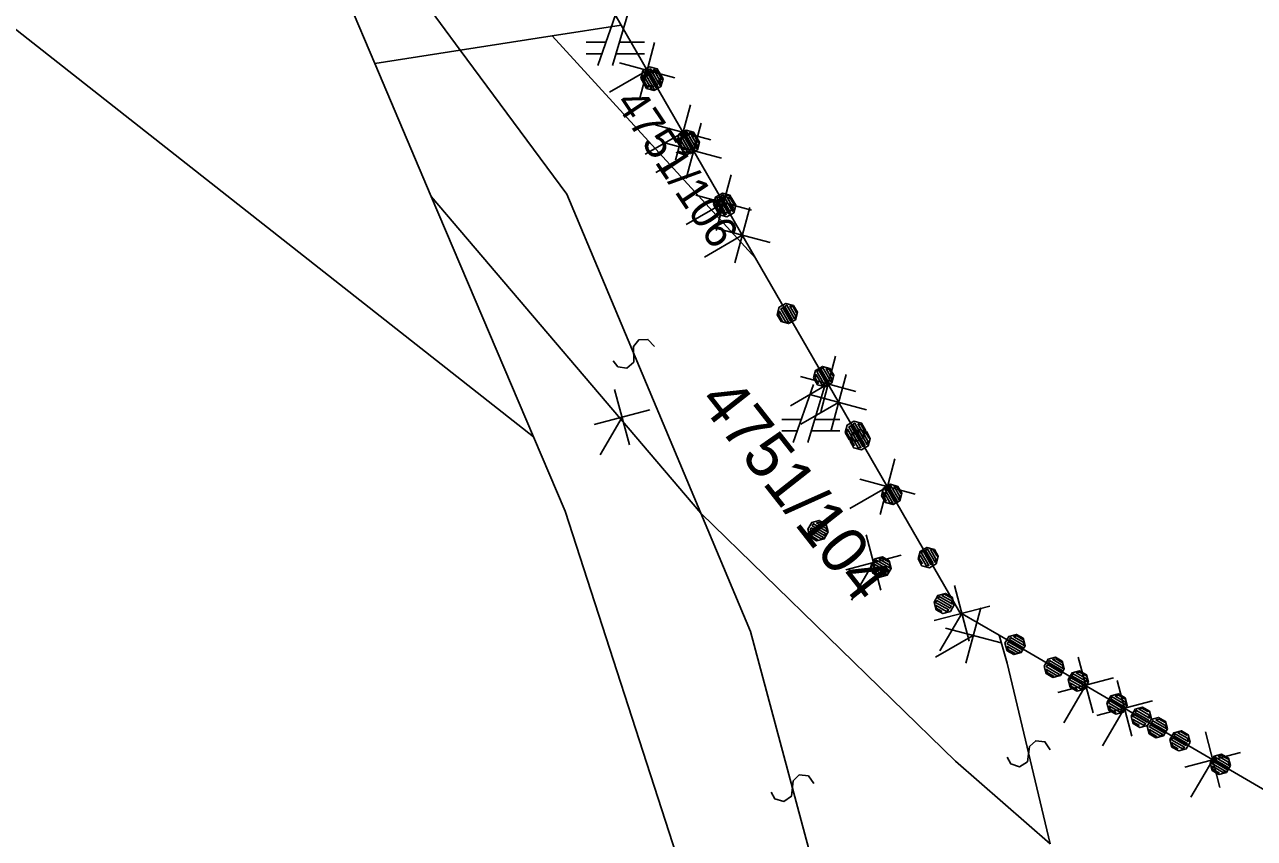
# Model space of a CAD drawing. Extents: x -266179 to -264727, y -1243225 to -1241702.
# Drawn here: x -264955.06 to -264912.71, y -1242293.44 to -1242265.42 of the extents above; entities that cross this region are included whole.
import ezdxf

# ---------------------------------------------------------------- set-up
doc = ezdxf.new("R2010")
doc.units = 0
for name, color, linetype in [('Vrstva 1', 7, 'Continuous'), ('Vrstva 19', 7, 'Continuous'), ('Vrstva 2', 7, 'Continuous'), ('Vrstva 21', 7, 'Continuous')]:
    doc.layers.add(name, color=color, linetype=linetype)

msp = doc.modelspace()

# ---------------------------------------------------------------- linework, layer by layer
at = {"layer": 'Vrstva 1'}
for p, q in [((-264937.54, -1242279.61), (-265000.5, -1242230.1)), ((-264938.49, -1242258.56), (-264934.52, -1242265.43)), ((-264943, -1242266.76), (-264943.91, -1242264.62)), ((-264934.62, -1242264.82), (-264935.32, -1242266.82)), ((-264934.82, -1242266.82), (-264934.22, -1242264.82)), ((-264936.9, -1242265.8), (-264934.52, -1242265.43)), ((-264934.52, -1242265.43), (-264929.89, -1242273.46)), ((-264940.06, -1242266.3), (-264936.9, -1242265.8)), ((-264936.9, -1242265.8), (-264940.06, -1242266.3)), ((-264929.89, -1242273.46), (-264936.9, -1242265.8)), ((-264936.9, -1242265.8), (-264929.89, -1242273.46)), ((-264935.04, -1242266.02), (-264935.72, -1242266.02)), ((-264933.72, -1242266.02), (-264934.58, -1242266.02)), ((-264943, -1242266.76), (-264940.06, -1242266.3)), ((-264940.06, -1242266.3), (-264943, -1242266.76)), ((-264935.72, -1242266.42), (-264935.18, -1242266.42)), ((-264934.7, -1242266.42), (-264933.72, -1242266.42)), ((-264941.06, -1242271.34), (-264943, -1242266.76)), ((-264931.78, -1242282.24), (-264941.06, -1242271.34)), ((-264937.54, -1242279.61), (-264941.06, -1242271.34)), ((-264941.06, -1242271.34), (-264931.78, -1242282.24)), ((-264929.89, -1242273.46), (-264922.85, -1242285.66)), ((-264927.89, -1242277.81), (-264928.59, -1242279.81)), ((-264928.09, -1242279.81), (-264927.49, -1242277.81)), ((-264928.31, -1242279.01), (-264928.99, -1242279.01)), ((-264926.99, -1242279.01), (-264927.85, -1242279.01)), ((-264936.45, -1242282.17), (-264937.54, -1242279.61)), ((-264928.99, -1242279.41), (-264928.45, -1242279.41)), ((-264927.97, -1242279.41), (-264926.99, -1242279.41)), ((-264931.05, -1242298.84), (-264936.45, -1242282.17)), ((-264923, -1242290.78), (-264931.78, -1242282.24)), ((-264931.78, -1242282.24), (-264923, -1242290.78)), ((-264922.85, -1242285.66), (-264921.5, -1242286.44)), ((-264921.5, -1242286.44), (-264909.83, -1242293.25)), ((-264919.74, -1242293.63), (-264923, -1242290.78)), ((-264923, -1242290.78), (-264919.74, -1242293.63))]:
    msp.add_line(p, q, dxfattribs=at)
at = {"layer": 'Vrstva 19'}
for p, q in [((-264938.49, -1242258.56), (-264934.52, -1242265.43)), ((-264934.52, -1242265.43), (-264929.89, -1242273.46)), ((-264929.89, -1242273.46), (-264922.85, -1242285.66)), ((-264922.85, -1242285.66), (-264921.5, -1242286.44)), ((-264921.5, -1242286.44), (-264909.83, -1242293.25))]:
    msp.add_line(p, q, dxfattribs=at)
for points in [[(-264933.143, -1242267.175), (-264933.213, -1242267.434), (-264933.447, -1242267.569), (-264933.707, -1242267.499), (-264933.841, -1242267.265), (-264933.772, -1242267.006), (-264933.538, -1242266.871), (-264933.278, -1242266.941), (-264933.143, -1242267.175), (-264933.173, -1242267.204), (-264933.293, -1242266.996), (-264933.402, -1242266.966), (-264933.202, -1242267.313), (-264933.242, -1242267.405), (-264933.511, -1242266.937), (-264933.581, -1242266.977), (-264933.316, -1242267.436), (-264933.38, -1242267.485), (-264933.645, -1242267.025), (-264933.714, -1242267.065), (-264933.45, -1242267.525), (-264933.544, -1242267.521), (-264933.759, -1242267.149), (-264933.793, -1242267.249), (-264933.653, -1242267.492)], [(-264933.078, -1242267.288), (-264933.148, -1242267.548), (-264933.382, -1242267.683), (-264933.641, -1242267.613), (-264933.776, -1242267.379), (-264933.706, -1242267.119), (-264933.472, -1242266.985), (-264933.213, -1242267.054), (-264933.078, -1242267.288), (-264933.108, -1242267.317), (-264933.227, -1242267.109), (-264933.337, -1242267.08), (-264933.137, -1242267.426), (-264933.176, -1242267.518), (-264933.446, -1242267.05), (-264933.515, -1242267.09), (-264933.251, -1242267.549), (-264933.315, -1242267.598), (-264933.58, -1242267.139), (-264933.649, -1242267.179), (-264933.384, -1242267.638), (-264933.479, -1242267.634), (-264933.693, -1242267.262), (-264933.728, -1242267.362), (-264933.588, -1242267.605)], [(-264931.891, -1242269.35), (-264931.96, -1242269.609), (-264932.194, -1242269.744), (-264932.454, -1242269.674), (-264932.589, -1242269.44), (-264932.519, -1242269.181), (-264932.285, -1242269.046), (-264932.025, -1242269.116), (-264931.891, -1242269.35), (-264931.93, -1242269.361), (-264932.05, -1242269.153), (-264932.159, -1242269.124), (-264931.96, -1242269.47), (-264931.989, -1242269.58), (-264932.268, -1242269.094), (-264932.338, -1242269.134), (-264932.058, -1242269.62), (-264932.128, -1242269.66), (-264932.407, -1242269.174), (-264932.476, -1242269.214), (-264932.197, -1242269.7), (-264932.306, -1242269.67), (-264932.506, -1242269.324), (-264932.535, -1242269.433), (-264932.415, -1242269.641)], [(-264931.825, -1242269.463), (-264931.895, -1242269.723), (-264932.129, -1242269.857), (-264932.388, -1242269.788), (-264932.523, -1242269.554), (-264932.453, -1242269.294), (-264932.219, -1242269.159), (-264931.96, -1242269.229), (-264931.825, -1242269.463), (-264931.865, -1242269.475), (-264931.985, -1242269.267), (-264932.094, -1242269.237), (-264931.894, -1242269.584), (-264931.924, -1242269.693), (-264932.203, -1242269.208), (-264932.272, -1242269.248), (-264931.993, -1242269.733), (-264932.062, -1242269.773), (-264932.342, -1242269.288), (-264932.411, -1242269.328), (-264932.132, -1242269.813), (-264932.241, -1242269.783), (-264932.44, -1242269.437), (-264932.47, -1242269.546), (-264932.35, -1242269.754)], [(-264930.638, -1242271.525), (-264930.707, -1242271.784), (-264930.941, -1242271.919), (-264931.201, -1242271.849), (-264931.336, -1242271.615), (-264931.266, -1242271.356), (-264931.032, -1242271.221), (-264930.772, -1242271.291), (-264930.638, -1242271.525), (-264930.692, -1242271.51), (-264930.812, -1242271.302), (-264930.911, -1242271.29), (-264930.722, -1242271.619), (-264930.751, -1242271.729), (-264931.011, -1242271.278), (-264931.08, -1242271.318), (-264930.82, -1242271.769), (-264930.89, -1242271.809), (-264931.149, -1242271.358), (-264931.224, -1242271.389), (-264930.964, -1242271.84), (-264931.053, -1242271.845), (-264931.258, -1242271.49), (-264931.302, -1242271.573), (-264931.183, -1242271.781)], [(-264930.572, -1242271.638), (-264930.642, -1242271.898), (-264930.876, -1242272.032), (-264931.136, -1242271.963), (-264931.27, -1242271.729), (-264931.201, -1242271.469), (-264930.967, -1242271.334), (-264930.707, -1242271.404), (-264930.572, -1242271.638), (-264930.627, -1242271.624), (-264930.747, -1242271.416), (-264930.846, -1242271.403), (-264930.656, -1242271.733), (-264930.686, -1242271.842), (-264930.945, -1242271.391), (-264931.015, -1242271.431), (-264930.755, -1242271.882), (-264930.824, -1242271.922), (-264931.084, -1242271.471), (-264931.158, -1242271.503), (-264930.899, -1242271.953), (-264930.988, -1242271.958), (-264931.193, -1242271.603), (-264931.237, -1242271.686), (-264931.117, -1242271.894)], [(-264928.449, -1242275.318), (-264928.518, -1242275.578), (-264928.752, -1242275.713), (-264929.012, -1242275.643), (-264929.147, -1242275.41), (-264929.077, -1242275.15), (-264928.843, -1242275.015), (-264928.584, -1242275.085), (-264928.449, -1242275.318), (-264928.478, -1242275.347), (-264928.598, -1242275.139), (-264928.708, -1242275.11), (-264928.508, -1242275.456), (-264928.547, -1242275.548), (-264928.817, -1242275.081), (-264928.886, -1242275.121), (-264928.621, -1242275.58), (-264928.686, -1242275.628), (-264928.951, -1242275.169), (-264929.02, -1242275.209), (-264928.755, -1242275.668), (-264928.849, -1242275.665), (-264929.064, -1242275.293), (-264929.098, -1242275.393), (-264928.958, -1242275.636)], [(-264927.194, -1242277.492), (-264927.263, -1242277.752), (-264927.497, -1242277.887), (-264927.757, -1242277.817), (-264927.892, -1242277.583), (-264927.822, -1242277.324), (-264927.588, -1242277.189), (-264927.329, -1242277.258), (-264927.194, -1242277.492), (-264927.233, -1242277.503), (-264927.353, -1242277.296), (-264927.463, -1242277.266), (-264927.263, -1242277.613), (-264927.292, -1242277.722), (-264927.572, -1242277.237), (-264927.641, -1242277.277), (-264927.361, -1242277.762), (-264927.431, -1242277.802), (-264927.711, -1242277.317), (-264927.78, -1242277.357), (-264927.5, -1242277.842), (-264927.609, -1242277.813), (-264927.809, -1242277.466), (-264927.838, -1242277.576), (-264927.718, -1242277.783)], [(-264926.107, -1242279.377), (-264926.177, -1242279.636), (-264926.41, -1242279.771), (-264926.67, -1242279.702), (-264926.805, -1242279.468), (-264926.735, -1242279.208), (-264926.502, -1242279.073), (-264926.242, -1242279.143), (-264926.107, -1242279.377), (-264926.137, -1242279.405), (-264926.257, -1242279.197), (-264926.366, -1242279.168), (-264926.166, -1242279.515), (-264926.205, -1242279.607), (-264926.475, -1242279.139), (-264926.544, -1242279.179), (-264926.279, -1242279.638), (-264926.344, -1242279.687), (-264926.609, -1242279.228), (-264926.678, -1242279.268), (-264926.413, -1242279.727), (-264926.507, -1242279.723), (-264926.722, -1242279.351), (-264926.757, -1242279.452), (-264926.617, -1242279.694)], [(-264925.939, -1242279.666), (-264926.008, -1242279.925), (-264926.242, -1242280.06), (-264926.502, -1242279.991), (-264926.637, -1242279.757), (-264926.567, -1242279.497), (-264926.333, -1242279.362), (-264926.074, -1242279.432), (-264925.939, -1242279.666), (-264925.993, -1242279.651), (-264926.113, -1242279.443), (-264926.213, -1242279.431), (-264926.023, -1242279.76), (-264926.052, -1242279.87), (-264926.312, -1242279.419), (-264926.381, -1242279.459), (-264926.121, -1242279.91), (-264926.191, -1242279.95), (-264926.451, -1242279.499), (-264926.525, -1242279.531), (-264926.265, -1242279.981), (-264926.354, -1242279.986), (-264926.559, -1242279.631), (-264926.603, -1242279.715), (-264926.483, -1242279.923)], [(-264924.852, -1242281.55), (-264924.921, -1242281.81), (-264925.155, -1242281.945), (-264925.415, -1242281.875), (-264925.55, -1242281.642), (-264925.48, -1242281.382), (-264925.247, -1242281.247), (-264924.987, -1242281.317), (-264924.852, -1242281.55), (-264924.892, -1242281.562), (-264925.012, -1242281.354), (-264925.121, -1242281.325), (-264924.921, -1242281.671), (-264924.95, -1242281.78), (-264925.23, -1242281.295), (-264925.299, -1242281.335), (-264925.019, -1242281.82), (-264925.089, -1242281.86), (-264925.369, -1242281.375), (-264925.438, -1242281.415), (-264925.158, -1242281.9), (-264925.267, -1242281.871), (-264925.467, -1242281.525), (-264925.497, -1242281.634), (-264925.377, -1242281.842)], [(-264927.461, -1242282.625), (-264927.392, -1242282.885), (-264927.527, -1242283.119), (-264927.787, -1242283.188), (-264928.02, -1242283.053), (-264928.09, -1242282.793), (-264927.955, -1242282.56), (-264927.695, -1242282.49), (-264927.461, -1242282.625), (-264927.473, -1242282.665), (-264927.68, -1242282.545), (-264927.79, -1242282.574), (-264927.443, -1242282.774), (-264927.431, -1242282.874), (-264927.899, -1242282.603), (-264927.939, -1242282.673), (-264927.48, -1242282.938), (-264927.512, -1242283.012), (-264927.97, -1242282.747), (-264928.01, -1242282.816), (-264927.552, -1242283.081), (-264927.635, -1242283.126), (-264928.007, -1242282.91), (-264927.987, -1242283.015), (-264927.744, -1242283.155)], [(-264923.597, -1242283.724), (-264923.666, -1242283.984), (-264923.9, -1242284.119), (-264924.16, -1242284.049), (-264924.295, -1242283.815), (-264924.225, -1242283.556), (-264923.991, -1242283.421), (-264923.732, -1242283.49), (-264923.597, -1242283.724), (-264923.652, -1242283.709), (-264923.772, -1242283.502), (-264923.871, -1242283.49), (-264923.681, -1242283.819), (-264923.71, -1242283.928), (-264923.97, -1242283.478), (-264924.039, -1242283.518), (-264923.779, -1242283.968), (-264923.849, -1242284.008), (-264924.109, -1242283.558), (-264924.183, -1242283.589), (-264923.923, -1242284.039), (-264924.012, -1242284.045), (-264924.217, -1242283.69), (-264924.262, -1242283.773), (-264924.142, -1242283.981)], [(-264925.288, -1242283.882), (-264925.219, -1242284.141), (-264925.354, -1242284.375), (-264925.614, -1242284.444), (-264925.847, -1242284.309), (-264925.917, -1242284.05), (-264925.782, -1242283.816), (-264925.522, -1242283.747), (-264925.288, -1242283.882), (-264925.317, -1242283.911), (-264925.525, -1242283.791), (-264925.634, -1242283.82), (-264925.288, -1242284.021), (-264925.258, -1242284.13), (-264925.743, -1242283.85), (-264925.783, -1242283.919), (-264925.298, -1242284.199), (-264925.339, -1242284.268), (-264925.823, -1242283.988), (-264925.863, -1242284.057), (-264925.379, -1242284.338), (-264925.488, -1242284.367), (-264925.834, -1242284.167), (-264925.805, -1242284.276), (-264925.597, -1242284.396)], [(-264923.115, -1242285.138), (-264923.046, -1242285.398), (-264923.181, -1242285.631), (-264923.441, -1242285.701), (-264923.674, -1242285.566), (-264923.744, -1242285.306), (-264923.609, -1242285.072), (-264923.349, -1242285.003), (-264923.115, -1242285.138), (-264923.17, -1242285.153), (-264923.378, -1242285.032), (-264923.47, -1242285.072), (-264923.141, -1242285.262), (-264923.111, -1242285.371), (-264923.562, -1242285.111), (-264923.602, -1242285.18), (-264923.151, -1242285.44), (-264923.192, -1242285.51), (-264923.642, -1242285.249), (-264923.69, -1242285.314), (-264923.24, -1242285.574), (-264923.315, -1242285.623), (-264923.67, -1242285.418), (-264923.667, -1242285.512), (-264923.459, -1242285.632)], [(-264920.672, -1242286.548), (-264920.603, -1242286.808), (-264920.738, -1242287.041), (-264920.997, -1242287.111), (-264921.231, -1242286.976), (-264921.301, -1242286.716), (-264921.165, -1242286.482), (-264920.906, -1242286.413), (-264920.672, -1242286.548), (-264920.683, -1242286.588), (-264920.891, -1242286.468), (-264921, -1242286.497), (-264920.654, -1242286.697), (-264920.642, -1242286.796), (-264921.11, -1242286.526), (-264921.15, -1242286.595), (-264920.691, -1242286.861), (-264920.722, -1242286.935), (-264921.181, -1242286.67), (-264921.221, -1242286.739), (-264920.762, -1242287.004), (-264920.846, -1242287.048), (-264921.218, -1242286.833), (-264921.197, -1242286.937), (-264920.955, -1242287.078)], [(-264919.326, -1242287.338), (-264919.258, -1242287.598), (-264919.394, -1242287.831), (-264919.654, -1242287.899), (-264919.887, -1242287.763), (-264919.956, -1242287.504), (-264919.819, -1242287.27), (-264919.56, -1242287.202), (-264919.326, -1242287.338), (-264919.338, -1242287.378), (-264919.545, -1242287.257), (-264919.655, -1242287.285), (-264919.309, -1242287.487), (-264919.298, -1242287.586), (-264919.764, -1242287.314), (-264919.804, -1242287.383), (-264919.347, -1242287.65), (-264919.378, -1242287.725), (-264919.836, -1242287.457), (-264919.876, -1242287.527), (-264919.419, -1242287.794), (-264919.502, -1242287.838), (-264919.873, -1242287.621), (-264919.853, -1242287.725), (-264919.611, -1242287.866)], [(-264918.499, -1242287.804), (-264918.43, -1242288.064), (-264918.565, -1242288.298), (-264918.824, -1242288.367), (-264919.058, -1242288.232), (-264919.128, -1242287.972), (-264918.992, -1242287.739), (-264918.733, -1242287.669), (-264918.499, -1242287.804), (-264918.528, -1242287.834), (-264918.736, -1242287.714), (-264918.845, -1242287.743), (-264918.499, -1242287.943), (-264918.469, -1242288.053), (-264918.954, -1242287.772), (-264918.994, -1242287.842), (-264918.509, -1242288.122), (-264918.549, -1242288.191), (-264919.034, -1242287.911), (-264919.074, -1242287.98), (-264918.589, -1242288.26), (-264918.699, -1242288.29), (-264919.045, -1242288.089), (-264919.016, -1242288.199), (-264918.808, -1242288.319)], [(-264917.158, -1242288.603), (-264917.09, -1242288.863), (-264917.226, -1242289.096), (-264917.486, -1242289.164), (-264917.719, -1242289.028), (-264917.788, -1242288.768), (-264917.651, -1242288.535), (-264917.392, -1242288.467), (-264917.158, -1242288.603), (-264917.187, -1242288.633), (-264917.395, -1242288.512), (-264917.504, -1242288.54), (-264917.158, -1242288.742), (-264917.13, -1242288.851), (-264917.613, -1242288.569), (-264917.654, -1242288.638), (-264917.17, -1242288.92), (-264917.21, -1242288.99), (-264917.694, -1242288.707), (-264917.734, -1242288.776), (-264917.251, -1242289.059), (-264917.36, -1242289.087), (-264917.706, -1242288.886), (-264917.677, -1242288.995), (-264917.469, -1242289.116)], [(-264916.326, -1242289.061), (-264916.257, -1242289.32), (-264916.392, -1242289.554), (-264916.651, -1242289.623), (-264916.885, -1242289.488), (-264916.955, -1242289.229), (-264916.819, -1242288.995), (-264916.56, -1242288.925), (-264916.326, -1242289.061), (-264916.381, -1242289.075), (-264916.589, -1242288.955), (-264916.68, -1242288.994), (-264916.352, -1242289.185), (-264916.322, -1242289.294), (-264916.772, -1242289.034), (-264916.813, -1242289.103), (-264916.362, -1242289.363), (-264916.402, -1242289.432), (-264916.853, -1242289.172), (-264916.901, -1242289.236), (-264916.451, -1242289.497), (-264916.526, -1242289.546), (-264916.881, -1242289.341), (-264916.877, -1242289.435), (-264916.67, -1242289.555)], [(-264915.775, -1242289.41), (-264915.707, -1242289.67), (-264915.843, -1242289.903), (-264916.103, -1242289.972), (-264916.336, -1242289.836), (-264916.404, -1242289.576), (-264916.268, -1242289.343), (-264916.008, -1242289.274), (-264915.775, -1242289.41), (-264915.787, -1242289.45), (-264915.994, -1242289.329), (-264916.103, -1242289.358), (-264915.758, -1242289.559), (-264915.746, -1242289.659), (-264916.213, -1242289.387), (-264916.253, -1242289.456), (-264915.795, -1242289.723), (-264915.827, -1242289.797), (-264916.285, -1242289.53), (-264916.325, -1242289.599), (-264915.867, -1242289.866), (-264915.951, -1242289.91), (-264916.322, -1242289.693), (-264916.302, -1242289.798), (-264916.06, -1242289.939)], [(-264914.99, -1242289.868), (-264914.922, -1242290.128), (-264915.058, -1242290.361), (-264915.318, -1242290.429), (-264915.551, -1242290.293), (-264915.62, -1242290.033), (-264915.484, -1242289.8), (-264915.224, -1242289.732), (-264914.99, -1242289.868), (-264915.045, -1242289.882), (-264915.252, -1242289.761), (-264915.345, -1242289.8), (-264915.016, -1242289.992), (-264914.988, -1242290.101), (-264915.437, -1242289.839), (-264915.477, -1242289.908), (-264915.028, -1242290.17), (-264915.068, -1242290.239), (-264915.517, -1242289.977), (-264915.566, -1242290.041), (-264915.117, -1242290.303), (-264915.192, -1242290.352), (-264915.546, -1242290.146), (-264915.543, -1242290.24), (-264915.336, -1242290.361)], [(-264913.607, -1242290.675), (-264913.539, -1242290.935), (-264913.675, -1242291.168), (-264913.935, -1242291.237), (-264914.168, -1242291.101), (-264914.236, -1242290.841), (-264914.1, -1242290.608), (-264913.84, -1242290.539), (-264913.607, -1242290.675), (-264913.636, -1242290.705), (-264913.843, -1242290.584), (-264913.953, -1242290.613), (-264913.607, -1242290.814), (-264913.578, -1242290.924), (-264914.062, -1242290.641), (-264914.102, -1242290.711), (-264913.619, -1242290.993), (-264913.659, -1242291.062), (-264914.143, -1242290.78), (-264914.183, -1242290.849), (-264913.699, -1242291.131), (-264913.809, -1242291.16), (-264914.154, -1242290.958), (-264914.126, -1242291.068), (-264913.918, -1242291.189)]]:
    msp.add_lwpolyline(points, dxfattribs=at)
at = {"layer": 'Vrstva 2'}
for p, q in [((-264940.06, -1242266.3), (-264943.08, -1242262.21)), ((-264940.06, -1242266.3), (-264936.39, -1242271.25)), ((-264936.39, -1242271.25), (-264931.78, -1242282.24)), ((-264931.78, -1242282.24), (-264930.07, -1242286.32)), ((-264930.07, -1242286.32), (-264927.17, -1242297.08)), ((-264921.5, -1242286.44), (-264921.23, -1242287.4)), ((-264921.23, -1242287.4), (-264919.74, -1242293.63))]:
    msp.add_line(p, q, dxfattribs=at)
for points in [[(-264933.374, -1242276.501), (-264933.596, -1242276.257), (-264933.915, -1242276.272), (-264934.091, -1242276.498), (-264934.082, -1242277.037), (-264934.32, -1242277.245), (-264934.631, -1242277.202), (-264934.796, -1242276.989)], [(-264919.744, -1242290.389), (-264919.923, -1242290.113), (-264920.24, -1242290.076), (-264920.451, -1242290.27), (-264920.529, -1242290.803), (-264920.798, -1242290.97), (-264921.098, -1242290.877), (-264921.226, -1242290.641)], [(-264927.883, -1242291.553), (-264928.07, -1242291.282), (-264928.388, -1242291.254), (-264928.593, -1242291.454), (-264928.656, -1242291.989), (-264928.919, -1242292.164), (-264929.222, -1242292.08), (-264929.357, -1242291.847)]]:
    msp.add_lwpolyline(points, dxfattribs=at)
at = {"layer": 'Vrstva 21'}
for p, q in [((-264938.49, -1242258.56), (-264934.52, -1242265.43)), ((-264934.52, -1242265.43), (-264929.89, -1242273.46)), ((-264933.368, -1242266.036), (-264933.88, -1242267.949)), ((-264932.668, -1242267.249), (-264934.58, -1242266.736)), ((-264933.624, -1242266.993), (-264934.923, -1242267.743)), ((-264932.132, -1242268.174), (-264932.646, -1242270.085)), ((-264931.433, -1242269.387), (-264933.345, -1242268.872)), ((-264931.764, -1242268.805), (-264932.278, -1242270.716)), ((-264932.389, -1242269.129), (-264933.689, -1242269.878)), ((-264932.021, -1242269.761), (-264933.32, -1242270.509)), ((-264931.065, -1242270.018), (-264932.977, -1242269.503)), ((-264930.73, -1242270.592), (-264931.243, -1242272.505)), ((-264930.987, -1242271.548), (-264932.286, -1242272.298)), ((-264930.03, -1242271.805), (-264931.943, -1242271.292)), ((-264930.092, -1242271.712), (-264930.604, -1242273.625)), ((-264929.392, -1242272.925), (-264931.304, -1242272.412)), ((-264930.348, -1242272.669), (-264931.647, -1242273.419)), ((-264929.89, -1242273.46), (-264922.85, -1242285.66)), ((-264927.136, -1242276.835), (-264927.648, -1242278.748)), ((-264926.772, -1242277.47), (-264927.286, -1242279.382)), ((-264927.392, -1242277.791), (-264928.691, -1242278.541)), ((-264926.436, -1242278.047), (-264928.348, -1242277.535)), ((-264934.743, -1242277.978), (-264934.232, -1242279.891)), ((-264926.073, -1242278.683), (-264927.985, -1242278.169)), ((-264933.531, -1242278.679), (-264935.444, -1242279.19)), ((-264927.029, -1242278.426), (-264928.329, -1242279.174)), ((-264934.487, -1242278.935), (-264935.238, -1242280.233)), ((-264925.092, -1242280.372), (-264925.604, -1242282.285)), ((-264925.348, -1242281.329), (-264926.647, -1242282.079)), ((-264924.392, -1242281.585), (-264926.304, -1242281.073)), ((-264926.086, -1242282.983), (-264925.574, -1242284.896)), ((-264924.874, -1242283.684), (-264926.786, -1242284.195)), ((-264925.83, -1242283.94), (-264926.581, -1242285.238)), ((-264923.037, -1242284.733), (-264922.534, -1242286.647)), ((-264921.828, -1242285.438), (-264923.743, -1242285.942)), ((-264922.136, -1242285.495), (-264922.648, -1242287.408)), ((-264922.786, -1242285.69), (-264923.542, -1242286.986)), ((-264922.85, -1242285.66), (-264921.5, -1242286.44)), ((-264921.436, -1242286.708), (-264923.348, -1242286.195)), ((-264922.392, -1242286.451), (-264923.691, -1242287.201)), ((-264921.5, -1242286.44), (-264909.83, -1242293.25)), ((-264918.776, -1242287.204), (-264918.264, -1242289.117)), ((-264917.564, -1242287.905), (-264919.476, -1242288.416)), ((-264917.433, -1242288.003), (-264916.93, -1242289.918)), ((-264918.52, -1242288.16), (-264919.271, -1242289.459)), ((-264916.224, -1242288.708), (-264918.139, -1242289.212)), ((-264917.182, -1242288.96), (-264917.938, -1242290.256)), ((-264914.4, -1242289.772), (-264913.897, -1242291.687)), ((-264913.191, -1242290.478), (-264915.106, -1242290.982)), ((-264914.148, -1242290.73), (-264914.904, -1242292.025))]:
    msp.add_line(p, q, dxfattribs=at)

# ---------------------------------------------------------------- texts
at = {"layer": 'Vrstva 1'}
for s, height, rotation, p in [('4751/106', 1.1, 303.8395, (-264934.754, -1242268.107)), ('4751/104', 1.6, 308.194, (-264931.891, -1242278.397))]:
    msp.add_text(s, height=height, rotation=rotation, dxfattribs=at).set_placement(p)

doc.saveas('drawing.dxf')
